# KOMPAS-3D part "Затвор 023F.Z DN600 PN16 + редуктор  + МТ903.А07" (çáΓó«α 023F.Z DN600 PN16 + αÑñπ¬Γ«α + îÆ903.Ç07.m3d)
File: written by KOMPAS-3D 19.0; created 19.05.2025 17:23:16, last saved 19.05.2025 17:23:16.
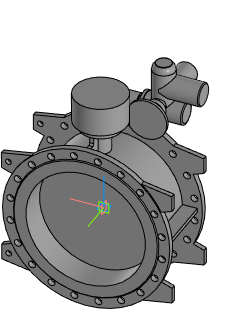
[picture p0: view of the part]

Document properties: Полное имя файла: Затвор 023F.Z DN600 PN16 + редуктор + МТ903.А07.a3d

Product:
- Part/product: Затвор 023F.Z DN600 PN16 + редуктор  + МТ903.А07
    Масса: 542.81
    source file: C:\Users\user122\Downloads\Затвор. Пример.cdw
  - Body: Тело 1
      Масса: 543.487

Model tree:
1. Операция без истории:1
